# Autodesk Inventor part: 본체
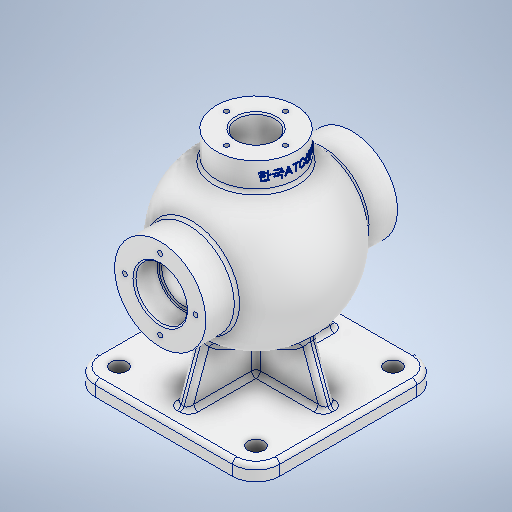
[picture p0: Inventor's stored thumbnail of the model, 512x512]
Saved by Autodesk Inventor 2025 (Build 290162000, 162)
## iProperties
Created: 2024-07
Part Number: 본체
Material: 알루미늄 6061
Document SubType Name: Modeling
Designer: anfro
Density: 2.7 g/cm^3
Appearance: 알루미늄 - 평지
Mass: 1526.72 g
Surface Area: 1173.82 cm^2
Volume: 565.453 cm^3
Author: anfro
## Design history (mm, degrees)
sketch "스케치1"
  geometry: L1 (62.5, 62.5)-(-62.5, 62.5); L2 (-62.5, 62.5)-(-62.5, -62.5); L3 (-62.5, -62.5)-(62.5, -62.5); L4 (62.5, -62.5)-(62.5, 62.5); L5 (62.5, 62.5)-(-62.5, -62.5); L6 (-62.5, 62.5)-(62.5, -62.5); 1 further point
  constraints: 12 end point, 2 midpoint, 2 parallel, 1 horizontal, 1 perpendicular
  dimensions: "d0" = 125 distance of L3.end L2.end; "d1" = 125 distance of L2.end L1.end
extrude "돌출1" new body sketch "스케치1" distance "d2" = 10; taper "d3" = 0 deg
node "작업 평면1"
sketch "스케치2" dims "d5" = 108, "d6" = 88
  geometry: L1 (-31, 65)-(31, 65); L2 (31, 65)-(31, 44.215); L3 (31, 44.215)-(-31, 44.215); L4 (-31, 44.215)-(-31, 65); L5 (-31, 65)-(31, 44.215); L6 (31, 65)-(-31, 44.215); L7 (0, 0)-(0, -131.339); L8 (-17.5, 65)-(17.5, 65); L9 (17.5, 65)-(17.5, 49); L10 (17.5, 49)-(-17.5, 49); L11 (-17.5, 49)-(-17.5, 65); L12 (-17.5, 65)-(17.5, 49); L13 (17.5, 65)-(-17.5, 49); L14 (0, 0)-(87.598, 0); L15 (31, -65)-(31, -44.215); L16 (17.5, -65)-(17.5, -49); L17 (17.5, -49)-(-17.5, -49); L18 (-17.5, -49)-(-17.5, -65); L19 (-17.5, -65)-(17.5, -65); L20 (-17.5, -65)-(17.5, -49); L21 (17.5, -65)-(-17.5, -49); L22 (31, -44.215)-(-31, -44.215); L23 (-31, -44.215)-(-31, -65); L24 (-31, -65)-(31, -44.215); L25 (31, -65)-(-31, -44.215); L26 (-31, -65)-(31, -65); L27 (15, 49)-(-15, 49); L28 (-15, 49)-(-15, 41.364); L29 (-15, 41.364)-(15, 41.364); L30 (15, 41.364)-(15, 49); L31 (-15, -49)-(-15, -41.364); L32 (15, -41.364)-(15, -49); L33 (-15, -41.364)-(15, -41.364); L34 (15, -49)-(-15, -49); 19 further points
  constraints: 68 end point, 14 symmetric about line, 6 parallel, 4 horizontal, 4 midpoint, 3 perpendicular, 2 coincident, 1 collinear, 1 point on line, 1 vertical, 1 vertical alignment, 8 other
  dimensions: "d7" = 62 distance of L1.start L1.end; "d8" = 65 distance from line of point (0, 0) L1; "d9" = 35 distance of L9.end L10.end; "d10" = 16 distance of L8.end L9.end; "d11" = 30 distance of L28.end L29.end
revolve "회전1" sketch "스케치2" stored, may be unused: angle "d12" = 90 deg
sketch "스케치4"
  geometry: L1 (-50.5, 4)-(50.5, 4); L2 (50.5, 4)-(50.5, -4); L3 (50.5, -4)-(-50.5, -4); L4 (-50.5, -4)-(-50.5, 4); L5 (-50.5, 4)-(50.5, -4); L6 (50.5, 4)-(-50.5, -4); L7 (-4, -50.5)-(4, -50.5); L8 (4, -50.5)-(4, 50.5); L9 (4, 50.5)-(-4, 50.5); L10 (-4, 50.5)-(-4, -50.5); L11 (-4, -50.5)-(4, 50.5); L12 (4, -50.5)-(-4, 50.5); L13 (62.5, -62.5)-(62.5, 62.5) reference; L14 (62.5, 62.5)-(-62.5, 62.5) reference; L15 (-62.5, 62.5)-(-62.5, -62.5) reference; L16 (-62.5, -62.5)-(62.5, -62.5) reference; 5 further points
  constraints: 24 end point, 4 midpoint, 4 parallel, 2 horizontal, 2 perpendicular
  dimensions: "d19" = 8 distance of L1.end L2.end; "d20" = 8 distance of L9.end L8.end; "d67" = 12 distance between parallel lines of L15 L4; "d70" = 12 distance between parallel lines of L16 L7
extrude "돌출3" join sketch "스케치4" stored distance "d23" = 10; taper "d24" = 0 deg
feature "면 기울기1" dims angle "d25" = 20 deg
sketch "스케치5"
  geometry: 1 further point
fillet "모깎기1" dims "d26" = 16
sketch "스케치6"
  geometry: C1 r 5.5 at (-46.5, 46.5); C2 r 5.5 at (46.5, 46.5); C3 r 5.5 at (46.5, -46.5); C4 r 5.5 at (-46.5, -46.5); A1 r 16 centre (-46.5, 46.5) between (-46.5, 62.5) and (-62.5, 46.5) reference; A2 r 16 centre (46.5, 46.5) between (62.5, 46.5) and (46.5, 62.5) reference; A3 r 16 centre (46.5, -46.5) between (46.5, -62.5) and (62.5, -46.5) reference; A4 r 16 centre (-46.5, -46.5) between (-62.5, -46.5) and (-46.5, -62.5) reference; 1 further point
  constraints: 4 centre point, 4 coincident
  dimensions: "d27" = 11 diameter of C1; "d28" = 11 diameter of C2; "d29" = 11 diameter of C3; "d30" = 11 diameter of C4
extrude "돌출4" cut sketch "스케치6" extent not by distance; stored distance "d31" = 0; taper "d32" = 0 deg
node "작업 평면2"
sketch "스케치7"
  geometry: C1 r 27 at (0, 0); 1 further point
  constraints: 1 centre point, 1 coincident
  dimensions: "d34" = 54 diameter of C1
extrude "돌출5" join sketch "스케치7" stored distance "d35" = 10; taper "d36" = 0 deg
sketch "스케치8"
  geometry: C1 r 13 at (0, 0); 1 further point
  constraints: 1 centre point, 1 coincident
  dimensions: "d37" = 26 diameter of C1
extrude "돌출6" cut sketch "스케치8" stored distance "d38" = 34.5; taper "d39" = 0 deg
chamfer "모따기1" distance "d40" = 1; stored, may be unused: second distance "d41" = 2, angle "d42" = 45 deg
fillet "모깎기2" dims "d43" = 0.6
fillet "모깎기3" dims "d44" = 3
fillet "모깎기4" dims "d45" = 3
fillet "모깎기5" dims "d46" = 3
fillet "모깎기6" dims "d47" = 3
node "작업 평면3"
sketch "스케치9"
  geometry: L1 (-14.44, 0.888)-(-14.44, -0.888); L2 (-14.44, -0.888)-(-3.56, -0.888); L3 (-3.56, -0.888)-(-3.56, 0.888); L4 (-3.56, 0.888)-(-14.44, 0.888); L5 (0, -27)-(0, 27) reference; 3 further points
  constraints: 2 midpoint, 1 horizontal alignment, 2 other
  dimensions: "d48" = 9 distance from line of L5 point (-9, 0.888)
feature "엠보싱1" sketch "스케치9" dims "d0" = 125, "d1" = 125, "d5" = 108, "d6" = 88, "d7" = 62, "d8" = 65, "d9" = 35, "d10" = 16, "d11" = 30, "d49" = 0.5, "d50" = 0
sketch "스케치10"
  geometry: C1 r 31 at (0, 0) reference; A1 r 24 centre (0, 0) between (0, 24) and (24, 0); 3 further points
  constraints: 4 point on circle, 2 horizontal alignment, 2 vertical alignment, 1 centre point, 1 coincident
  dimensions: "d51" = 48 diameter of A1
hole "구멍1" sketch "스케치10" at (0, 24), (24, 0), (0, -24), (-24, 0) diameter "d52" = 3.242; stored, may be unused: countersink angle "d56" = 90 deg, drill point angle "d58" = 118 deg; dims "d53" = 12, "d54" = 4, "d55" = 2, "d57" = 15
sketch "스케치11"
  geometry: A1 r 20 centre (0, 0) between (-20, 0) and (0, 20); 3 further points
  constraints: 4 point on circle, 2 horizontal alignment, 2 vertical alignment, 1 centre point, 1 coincident
  dimensions: "d59" = 40 diameter of A1
hole "구멍2" sketch "스케치11" at (-20, 0), (0, 20), (20, 0), (0, -20) diameter "d60" = 3.242; stored, may be unused: countersink angle "d64" = 90 deg, drill point angle "d66" = 118 deg; dims "d61" = 9, "d62" = 4, "d63" = 2, "d65" = 11
fillet "모깎기7" dims "d68" = 3
feature "Ҋ耀Ҍ耀Ҏ耀Ґ耀Ғ耀Ҕ耀Җ耀Ҙ耀" dims "d0" = 125, "d1" = 125, "d2" = 10, "d3" = 0, "d4" = 85, "d5" = 108, "d6" = 88, "d7" = 62, "d8" = 65, "d9" = 35, "d10" = 16, "d11" = 30, "d12" = 90 deg, "d19" = 8, "d20" = 8, "d23" = 10, "d24" = 0, "d25" = 20 deg, "d26" = 16, "d27" = 11, "d28" = 11, "d29" = 11, "d30" = 11, "d31" = 0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
node "솔리드1"
mirror "미러1"
feature "A9D066F2-1C7D-4E18-AEED-F7BC21143FA4" dims "d52" = 3.242, "d53" = 12, "d54" = 4, "d55" = 2, "d56" = 90 deg, "d57" = 15, "d58" = 118 deg
